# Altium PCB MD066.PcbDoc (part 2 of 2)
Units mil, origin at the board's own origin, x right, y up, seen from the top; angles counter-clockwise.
Board outline 4255 x 2850 mil, 4 copper layers (Top Layer, Ground, Power, Bottom Layer), stack 61.6 mil thick; 158 components, 78 nets, 405 pads, 639 vias.
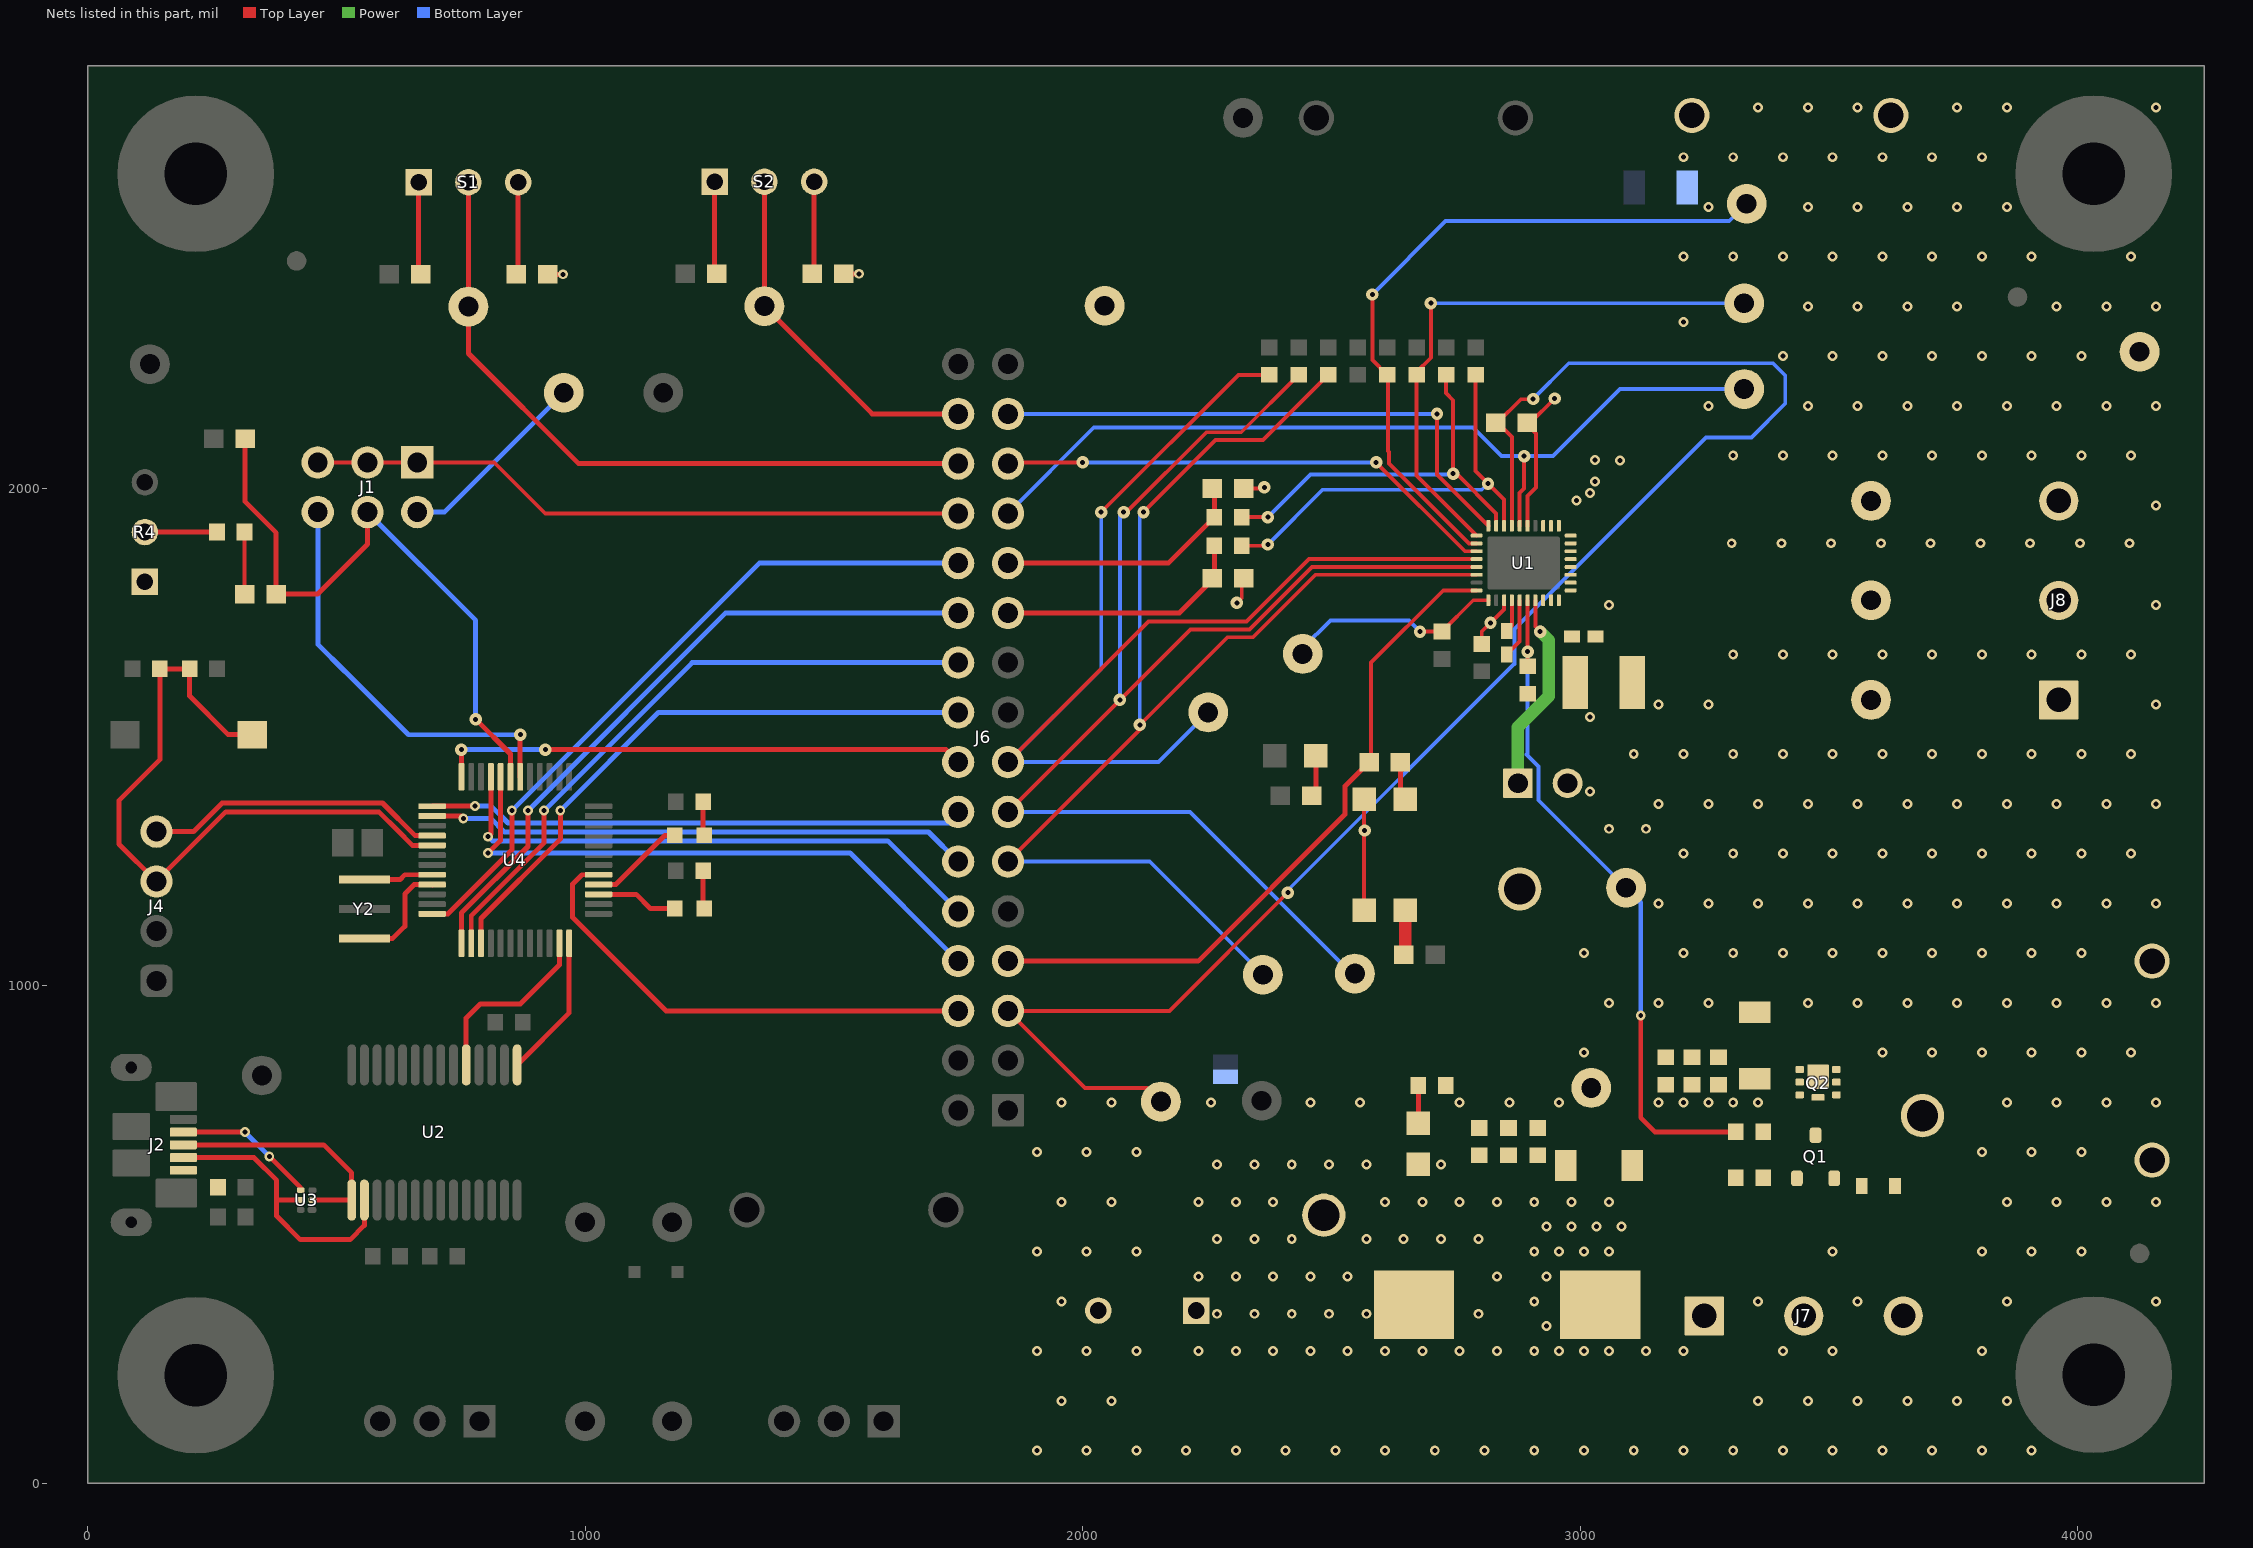
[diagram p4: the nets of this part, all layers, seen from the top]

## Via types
v1: diameter 20, hole 10, Top Layer to Bottom Layer, tented both sides, 600 vias
v2: diameter 25, hole 10, Top Layer to Bottom Layer, tented both sides, 30 vias
v3: diameter 19.68, hole 7.87, Top Layer to Bottom Layer, tented both sides, 8 vias
v4: diameter 25, hole 10, Top Layer to Bottom Layer, 1 vias

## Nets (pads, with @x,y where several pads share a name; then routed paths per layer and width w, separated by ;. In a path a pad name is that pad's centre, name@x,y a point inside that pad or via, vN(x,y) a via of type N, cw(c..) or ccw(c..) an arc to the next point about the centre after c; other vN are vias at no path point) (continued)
AVDD: C5.2 D1.1 D2.1 R1.2 R2.2 R4.1 R10.2 R13.2 R14.2 TP11.1 U1.3 U1.23 | length 803.3
  Top Layer w7.87: v2(2310,1770) 2320.06,1780.06 R14.2@2320.06,1820 ; R13.2@2320.06,2000 2362.84,2000 v2(2365.34,2002.5) ; D1.1@2566.16,1152.5 D2.1@2566.16,1375 ; C5.2@2802.5,1687.56 2802.5,1712.3 v2(2820,1729.8) 2847.26,1757.07 U1.3@2847.26,1775.39 ; U1.23@2894.51,1925 2894.51,1984.74 2911.81,2002.04 2911.81,2110.28 2889.59,2132.5 2900.67,2132.5 v2(2949.16,2180.99)
  Top Layer w10: R1.2@920.5,2430.7 v1(955.44,2430.7) ; R2.2@1515.5,2431.7 v1(1550.44,2431.7)
  Power w7.87: v2(2567.02,1312.5) v2@2567.02,1313
BRAKE: J6.27 U1.31 | length 1017.2
  Top Layer w7.87: J6.27@1850,2050 1852.5,2052.5 v4(2000,2052.5) ; v2(2590,2052.5) 2768.68,1873.82 U1.31@2792.15,1873.82
  Bottom Layer w7.87: v4(2000,2052.5) v2(2590,2052.5)
BRAKE_SW: J6.28 S1.2 TP2.1 | length 1420.5
  Top Layer w10: S1.2@765.44,2615.7 TP2.1@765.44,2365.7 765.44,2271.54 986.97,2050 J6.28@1750,2050
CPH: C7.1 U1.5 | length 119.9
  Top Layer w7.87: C7.1@2852.5,1666.38 2878.76,1692.64 U1.5@2878.76,1775.39
CPL: C7.2 U1.4 | length 88.2
  Top Layer w7.87: C7.2@2852.5,1713.62 2863.01,1724.13 U1.4@2863.01,1775.39 2863.01,1753.32
DACOUT1: J6.11 R28.1 TP15.1 U1.34 | length 2736.6
  Top Layer w7.87: J6.11@1850,1250 2117.5,1517.5 2115,1520 v2(2115,1525) 2291,1701 2342.48,1701 2468.05,1826.57 U1.34@2792.15,1826.57 ; v2(2122.5,1952.5) 2267.34,2097.34 2362.5,2097.34 R28.1@2493.6,2228.44
  Top Layer w10: J6.11@1850,1250 J6.11@1875,1250
  Bottom Layer w7.87: J6.11@1850,1250 2135,1250 TP15.1@2362.5,1022.5 ; v2(2115,1525) 2115,1945 v2(2122.5,1952.5)
DACOUT2: J6.13 R29.1 TP16.1 U1.33 | length 2824.9
  Top Layer w7.87: J6.13@1850,1350 v2(2075,1575) 2216.75,1716.75 2335.95,1716.75 2461.52,1842.32 U1.33@2792.15,1842.32 ; v2(2082.5,1952.5) 2088.12,1952.5 2248.71,2113.09 2318.95,2113.09 R29.1@2434.3,2228.44
  Bottom Layer w7.87: J6.13@1850,1350 2215.62,1350 2540.62,1025 TP16.1@2547.5,1025 ; v2(2075,1575) 2075,1945 v2(2082.5,1952.5)
DACOUT2/SOX: J6.15 R27.1 TP17.1 U1.32 | length 2587.1
  Top Layer w7.87: J6.15@1850,1450 2132.5,1732.5 2329.43,1732.5 2455,1858.07 U1.32@2792.15,1858.07 ; v2(2037.5,1952.5) 2313.44,2228.44 R27.1@2375,2228.44
  Bottom Layer w7.87: v2(2037.5,1952.5) 2037.5,1637.5 J6.15@1850,1450 2152.5,1450 TP17.1@2252.5,1550
DIR: J6.29 U1.28 | length 1130.4
  Top Layer w7.87: v2(2712.5,2150) 2712.5,2028.12 2815.62,1925 U1.28@2815.77,1925
  Bottom Layer w7.87: J6.29@1850,2150 v2(2712.5,2150)
DIR_SW: J6.30 S2.2 TP3.1 | length 729.3
  Top Layer w10: S2.2@1360.44,2616.7 TP3.1@1360.44,2366.7 1577.14,2150 J6.30@1750,2150
DM: J2.2 U2.16 U3.5 | length 585.4
  Top Layer w10: J2.2@192.22,655 334.14,655 380,609.14 380,570 ; U3.5@428.19,569.59 380.41,569.59 380,570 ; U2.16@556.23,569.59 556.23,518.73 527.5,490 427.5,490 380,537.5 380,570
DP: J2.3 U2.15 U3.2 | length 495.3
  Top Layer w10: J2.3@192.22,680.59 474.41,680.59 530.64,624.36 U2.15@530.64,569.59 U3.2@451.81,569.59
DVDD: C3.2 TP12.1 U1.1 | length 443.3
  Top Layer w7.87: v2(2678.37,1712.5) 2722.44,1712.5 C3.2@2722.5,1712.56 2785.33,1775.39 U1.1@2815.77,1775.39
  Bottom Layer w7.87: TP12.1@2442.5,1667.5 2442.5,1679 2498.5,1735 2655.87,1735 v2(2678.37,1712.5)
EXT_CLK: R24.1 TP8.1 U1.30 | length 1424.5
  Top Layer w7.87: v2(2582.5,2390) 2582.5,2258.14 R24.1@2612.2,2228.44 2614.31,2226.33 2614.31,2075 2615.71,2073.6 2615.71,2050.45 2776.6,1889.57 U1.30@2792.15,1889.57
  Bottom Layer w7.87: v2(2582.5,2390) 2730,2537.5 3300,2537.5 TP8.1@3335,2572.5
EXT_SPEED: J1.2 TP1.1 | length 409.1
  Top Layer w10: J1.2@662.5,1937.27 J1.2@662.5,1952.5
  Bottom Layer w10: J1.2@662.5,1952.5 716.95,1952.5 TP1.1@956.95,2192.5
EXT_WD: R23.1 TP7.1 U1.29 | length 1159
  Top Layer w7.87: v2(2700,2372.5) v2(2700,2372.5) 2700.04,2262.92 2671.5,2234.38 R23.1@2671.5,2228.44 2671.5,2025.96 U1.29@2792.15,1905.32
  Bottom Layer w7.87: v2(2700,2372.5) TP7.1@3330,2372.5
FG: J6.5 R10.1 TP35.1 U1.25 | length 3408.8
  Top Layer w7.87: TP35.1@2157.5,767.5 2130,795 2005,795 J6.5@1850,950 2175,950 v2(2412.5,1187.5) ; U1.25@2863.01,1925 2863.01,2103.96 2834.47,2132.5 2881.37,2179.41 2905,2179.41 v2(2905.59,2180)
  Bottom Layer w7.87: v2(2412.5,1187.5) 2412.5,1192.36 2867.64,1647.5 2868.19,1647.5 2868.19,1717.5 3253.19,2102.5 3344.38,2102.5 3412.5,2170.62 3412.5,2227.5 3388.19,2251.81 2977.41,2251.81 v2(2905.59,2180)
ID: J2.4 U3.4 | length 287.3
  Top Layer w10: J2.4@192.22,706.18 v1(316.27,706.18) ; v1(365,657.5) 428.19,594.31 U3.4@428.19,589.28
  Bottom Layer w10: v1(316.27,706.18) 364.95,657.5 v1(365,657.5)
MCX_SCL: J6.23 R13.1 R15.1 | length 510.8
  Top Layer w10: J6.23@1850,1850 2172.44,1850 R15.1@2264.94,1942.5 R13.1@2264.94,2000
MCX_SDA: J6.21 R14.1 R16.1 | length 508.9
  Top Layer w10: J6.21@1850,1750 2194.94,1750 2264.94,1820 R16.1@2264.94,1885
MSP_A1_P1.1: J6.12 U4.2 | length 1094.7
  Top Layer w10: U4.2@693.3,1341.67 750.24,1341.67 v1(755,1336.91)
  Bottom Layer w10: v1(755,1336.91) 810.31,1336.91 837.6,1309.63 1690.37,1309.63 J6.12@1750,1250
MSP_A2_P1.2: J6.14 U4.1 | length 1070.7
  Top Layer w10: U4.1@693.3,1361.36 v1(778.64,1361.36)
  Bottom Layer w10: v1(778.64,1361.36) 811.14,1361.36 845,1327.5 J6.14@1750,1327.5
MSP_A3_P1.3: J6.16 U4.48 | length 1064.6
  Top Layer w10: U4.48@751.37,1419.43 U4.48@751.37,1420.41 v2(751.37,1475) ; v2(920,1475) 1725,1475 J6.16@1750,1450
  Bottom Layer w10: v2(751.37,1475) v2(920,1475)
MSP_ALARM_P3.2: J6.10 U4.45 | length 1130.1
  Top Layer w10: v1(805,1300) 810.43,1305.43 810.43,1419.43 U4.45@811.33,1420.33
  Bottom Layer w10: v1(805,1300) 813.25,1291.75 1608.25,1291.75 J6.10@1750,1150
MSP_CLK_P4.5: J6.20 U4.14 | length 1282.1
  Top Layer w10: U4.14@771.06,1086.75 771.06,1141.3 917.5,1287.74 v1(917.5,1352.5)
  Bottom Layer w10: v1(917.5,1352.5) 1215,1650 J6.20@1750,1650
MSP_FGOUT_P2.1: J6.6 U4.29 | length 978.8
  Top Layer w10: U4.29@1025.98,1223.56 993.56,1223.56 975,1205 975,1137.5 1162.5,950 J6.6@1750,950
MSP_LED0_P2.2: D6.2 U4.28 | length 195.1
  Top Layer w10: U4.28@1025.98,1203.88 1061.68,1203.88 1160.49,1302.7 D6.2@1180.11,1302.7
MSP_LED1_P2.2: D7.2 U4.27 | length 166
  Top Layer w10: U4.27@1025.98,1184.19 1102.5,1184.19 1131.1,1155.59 D7.2@1180.11,1155.59
MSP_nFAULT_P3.3: J6.8 U4.44 | length 1197.4
  Top Layer w10: v1(805,1267.5) 829.63,1292.13 829.63,1418.94 U4.44@830.11,1419.43
  Bottom Layer w10: v1(805,1267.5) 1532.5,1267.5 J6.8@1750,1050
MSP_RX_P4.3: U2.5 U4.23 | length 370.2
  Top Layer w10: U2.5@760.96,841.24 760.96,935.49 789.25,963.78 869.75,963.78 948.22,1042.25 U4.23@948.22,1086.75
MSP_SBWTCK: J4.4 U4.4 | length 617.6
  Top Layer w10: J4.4@145.74,1302.3 137.86,1310.18 212.58,1310.18 270.27,1367.87 592.8,1367.87 658.37,1302.3 U4.4@693.3,1302.3
MSP_SBWTDIO/nRST: C14.1 J4.3 R31.1 S4.1 U4.5 | length 1406.7
  Top Layer w10: S4.1@330.96,1505.27 282.5,1505.27 204.94,1582.83 R31.1@204.94,1637.5 C14.1@145.06,1637.5 145.06,1455 62.5,1372.44 62.5,1285.54 137.86,1210.18 277.68,1350 585.35,1350 624.97,1310.37 ; 625.02,1310.37 650.41,1284.98 ; 650.41,1284.94 652.73,1282.62 U4.5@693.3,1282.62
MSP_SIMO/SDA_P4.6: J6.22 U4.13 | length 1350.7
  Top Layer w10: U4.13@751.37,1086.75 751.37,1146.89 885,1280.52 v1(885,1352.5)
  Bottom Layer w10: v1(885,1352.5) 1282.5,1750 J6.22@1750,1750
MSP_SOMI/SCL_P4.7: J6.24 U4.12 | length 1396.5
  Top Layer w10: U4.12@694.21,1145.73 693.3,1144.82 724.03,1144.82 852.5,1273.3 v1(852.5,1352.5)
  Bottom Layer w10: v1(852.5,1352.5) 1350,1850 J6.24@1750,1850
MSP_STE_P4.4: J6.18 U4.15 | length 1213.5
  Top Layer w10: U4.15@790.74,1086.75 790.74,1135.71 950,1294.96 v1(950,1352.5)
  Bottom Layer w10: v1(950,1352.5) 1147.5,1550 J6.18@1750,1550
MSP_TB0.1: J1.6 U4.42 | length 833.3
  Top Layer w10: U4.42@869.48,1420.41 869.48,1505 v2(869.75,1505.27)
  Bottom Layer w10: J1.6@462.5,1952.5 462.5,1686.83 517.19,1632.15 517.73,1632.15 644.88,1505 869.48,1505 v2(869.75,1505.27)
MSP_TX_P4.2: U2.1 U4.24 | length 288.8
  Top Layer w10: U2.1@863.32,841.24 967.91,945.83 U4.24@967.91,1086.75
MSP_XIN_P2.7: U4.8 Y2.1 | length 141.2
  Top Layer w10: Y2.1@556.22,1213.72 627.85,1213.72 637.69,1223.56 U4.8@693.3,1223.56
MSP_XOUT_P2.6: U4.9 Y2.3 | length 221.8
  Top Layer w10: Y2.3@556.83,1095 Y2.3@556.22,1095.61 613.11,1095.61 637.5,1120 637.5,1185 656.38,1203.88 693.3,1203.88 U4.9@693.3,1202.97
NetC17_1: C17.1 C18.1 C19.1 C20.1 L4.1 Q2.1 Q2.2 Q2.5 Q2.6 Q2.7
  other v1: 2908,266 2958,266 3008,266 3058,266 2933,316 2908,366 2933,416 2908,466 2958,466 3008,466 3058,466 2933,516 2983,516 3033,516 3083,516 3158,766 3208,766 3258,766 3308,766 3358,766
NetD1_2: D1.2 R17.2 | length 90.5
  Top Layer w25: D1.2@2648.84,1152.5 2648.84,1063.6 R17.2@2649.94,1062.5
NetD2_2: D2.2 R18.2 | length 79.1
  Top Layer w10: R18.2@2639,1450 2639,1384.84 D2.2@2648.84,1375
NetD3_2: D3.2 R19.2 | length 83.5
  Top Layer w10: R19.2@2460.48,1382.5 2468.84,1390.86 D3.2@2468.84,1462.5
NetD4_2: D4.2 R20.2 | length 76.2
  Top Layer w10: D4.2@2675,723.84 R20.2@2675,800
NetD6_1: D6.1 R32.1 | length 68.3
  Top Layer w10: R32.1@1237.2,1370.2 1237.2,1304.67 D6.1@1239.17,1302.7
NetD7_1: D7.1 R33.1 | length 76.7
  Top Layer w10: R33.1@1237.2,1231.43 1237.2,1157.56 D7.1@1239.17,1155.59
NetD8_2: D8.2 Q1.2
NetJ2_1: J2.1 L3.2
NetQ1_1: Q1.1 R35.1
NetQ1_3: Q1.3 Q2.3 R34.2
NetR1_1: R1.1 S1.3 | length 185
  Top Layer w10: R1.1@865.44,2430.7 S1.3@865.44,2615.7
NetR2_1: R2.1 S2.3 | length 185
  Top Layer w10: R2.1@1460.44,2431.7 S2.3@1460.44,2616.7
NetR4_2: R4.2 R5.2 | length 144.9
  Top Layer w10: R4.2@115,1912.5 R5.2@259.94,1912.5
NetR5_1: R5.1 R9.2 | length 125.4
  Top Layer w7.87: R5.1@315.06,1912.5 315.06,1788.44 R9.2@316,1787.5
NetR6_2: R6.2 S1.1 | length 185
  Top Layer w10: S1.1@665.44,2615.7 665.44,2430.76 R6.2@665.5,2430.7
NetR7_2: R7.2 S2.1 | length 185
  Top Layer w10: R7.2@1260.44,2431.7 S2.1@1260.44,2616.7
nFAULT: J6.7 R18.1 U1.36 | length 1401.2
  Top Layer w7.87: R18.1@2579.94,1450 2579.94,1650.02 2725,1795.08 U1.36@2792.15,1795.08
  Top Layer w10: J6.7@1850,1050 2232.5,1050 2527.5,1345 2527.5,1401.79 2575.71,1450 R18.1@2579.94,1450
OUTA: J8.1 TP5.1 U1.11 U1.12
OUTB: J8.2 TP6.1 U1.14 U1.15
OUTC: J8.3 TP9.1 U1.17 U1.18
PGND: C4.2 C6.2 C16.2 C17.2 C18.2 C19.2 C20.2 C21.2 C22.2 C23.2 C24.2 J7.2 NT2.2 R20.1 R35.2 R36.2 TP25.1 TP28.1 TP28.2 TP29.1 TP29.2 TP34.1 U1.10 U1.13 U1.16 U1.19
  other v1: 1908,66 2008,66 2108,66 2208,66 2308,66 2408,66 2508,66 2608,66 2708,66 2808,66 2908,66 3008,66 3108,66 3208,66 3308,66 3408,66 3508,66 3608,66 3708,66 3808,66 3908,66 1958,166 2058,166 3358,166 3458,166 3558,166 3658,166 3758,166 3858,166 1908,266 2008,266 2108,266 3408,266 3508,266 3808,266 1958,366 3358,366 3558,366 3858,366 4158,366 1908,466 2008,466 2108,466 3508,466 3808,466 3908,466 4008,466 1958,566 2058,566 3058,566 3858,566 3958,566 4058,566 4158,566 1908,666 2008,666 2108,666 3808,666 3908,666 4008,666 1958,766 2058,766 2258,766 2458,766 2558,766 2758,766 2858,766 2958,766 3858,766 3958,766 4058,766 4158,766 3008,866 3608,866 3708,866 3808,866 3908,866 4008,866 4108,866 3058,966 3158,966 3258,966 3458,966 3558,966 3658,966 3758,966 3858,966 3958,966 4058,966 4158,966 3008,1066 3208,1066 3308,1066 3408,1066 3508,1066 3608,1066 3708,1066 3808,1066 3908,1066 4008,1066 3158,1166 3258,1166 3358,1166 3458,1166 3558,1166 3658,1166 3758,1166 3858,1166 3958,1166 4058,1166 4158,1166 3208,1266 3308,1266 3408,1266 3508,1266 3608,1266 3708,1266 3808,1266 3908,1266 4008,1266 4108,1266 3158,1366 3258,1366 3358,1366 3458,1366 3558,1366 3658,1366 3758,1366 3858,1366 3958,1366 4058,1366 4158,1366 3108,1466 3208,1466 3308,1466 3408,1466 3508,1466 3608,1466 3708,1466 3808,1466 3908,1466 4008,1466 4108,1466 3158,1566 3258,1566 4158,1566 3308,1666 3408,1666 3508,1666 3608,1666 3708,1666 3808,1666 3908,1666 4008,1666 4108,1666 3058,1766 4158,1766 3305,1890 3405,1890 3505,1890 3605,1890 3705,1890 3805,1890 3905,1890 4005,1890 4105,1890 4158,1966 3308,2066 3408,2066 3508,2066 3608,2066 3708,2066 3808,2066 3908,2066 4008,2066 4108,2066 3258,2166 3458,2166 3558,2166 3658,2166 3758,2166 3858,2166 3958,2166 4058,2166 4158,2166 3408,2266 3508,2266 3608,2266 3708,2266 3808,2266 3908,2266 4008,2266 3208,2335 3458,2366 3558,2366 3658,2366 3758,2366 3958,2366 4058,2366 4158,2366 3208,2466 3308,2466 3408,2466 3508,2466 3608,2466 3708,2466 3808,2466 3908,2466 4108,2466 3258,2566 3458,2566 3558,2566 3658,2566 3758,2566 3858,2566 3208,2666 3308,2666 3408,2666 3508,2666 3608,2666 3708,2666 3808,2666 3358,2766 3458,2766 3558,2766 3758,2766 3858,2766 4158,2766
POT: C2.1 J1.4 R9.1 U4.43 | length 1279
  Top Layer w10: C2.1@316.5,2100 316.5,1973.5 379,1911 R9.1@379,1787.5 461.85,1787.5 562.5,1888.15 J1.4@562.5,1952.5 ; v2(780,1536.14) 849.8,1466.34 U4.43@849.8,1420.41
  Bottom Layer w10: J1.4@562.5,1952.5 780,1735 v2(780,1536.14)
SCL: R15.2 R22.1 U1.27 | length 817
  Top Layer w7.87: R15.2@2320.06,1942.5 v2(2372.5,1942.5) ; R22.1@2730.8,2228.44 2730.8,2191.7 2745,2177.5 v2(2745,2030) 2751.52,2030 2831.52,1950 U1.27@2831.52,1925
  Bottom Layer w7.87: v2@2379.38,1942.5 v2(2372.5,1942.5) 2458.19,2028.19 2743.19,2028.19 v2(2745,2030)
SDA: R16.2 R21.1 U1.26 | length 873.8
  Top Layer w7.87: R16.2@2320.06,1885 2370,1885 v2(2372.5,1887.5) ; R21.1@2790.1,2228.44 2790.1,2034.9 v2(2815,2010) 2847.26,1977.74 U1.26@2847.26,1925
  Bottom Layer w7.87: v2(2372.5,1887.5) 2482.5,1997.5 2802.5,1997.5 v2(2815,2010)
SPEED/WAKE: J6.25 TP14.1 U1.24 | length 1774.8
  Top Layer w7.87: U1.24@2878.76,1925 2878.76,1991.26 2887.5,2000 v2(2887.5,2065)
  Bottom Layer w7.87: J6.25@1850,1950 2022.5,2122.5 2785,2122.5 2842.5,2065 v2(2887.5,2065) 2945.62,2065 3080.62,2200 TP14.1@3330,2200
SPEED_IN: J1.1 J1.3 J1.5 J6.26 | length 1338.2
  Top Layer w7.87: J1.5@462.5,2052.5 J1.3@562.5,2052.5 J1.1@662.5,2052.5 817.27,2052.5 919.77,1950 J6.26@1750,1950 J6.26@1744.19,1944.19
VBAT: D8.1 J7.3 Q2.4 Q2.8 TP23.1
VCP: C1.1 R34.1 TP13.1 U1.6 | length 1379.6
  Top Layer w7.87: U1.6@2894.51,1775.39 v2(2894.51,1672.01) 2894.51,1642.99 C1.1@2894.94,1642.56 C1.1@2902.5,1650.12
  Top Layer w10: v1(3122.11,940.29) 3122.11,735.08 3150.55,706.64 R34.1@3313.4,706.64
  Bottom Layer w7.87: v2(2894.51,1672.01) 2894.51,1467.33 2892.5,1465.32 2916.73,1441.09 2916.73,1373.27 TP13.1@3092.5,1197.5
  Bottom Layer w10: TP13.1@3092.5,1197.5 3122.11,1167.89 v1(3122.11,940.29)
VIN_AVDD: JP1.1 TP10.1 U1.7 | length 405.1
  Top Layer w7.87: U1.7@2910.26,1775.39 2910.26,1722.24 v2(2920,1712.5)
  Power w25: JP1.1@2875,1407.5 2875,1520.22 2937.5,1582.72 2937.5,1695 v2(2920,1712.5)
VM: C1.2 C4.1 C6.1 C16.1 C21.1 C22.1 C23.1 C24.1 D4.1 J7.1 JP1.2 L4.2 TP24.1 U1.8 U1.9 U1.20 U1.21
  other v1: 2233,266 2308,266 2383,266 2458,266 2533,266 2608,266 2683,266 2758,266 2833,266 3133,266 3208,266 2270.5,341 2345.5,341 2420.5,341 2495.5,341 2570.5,341 2795.5,341 2233,416 2308,416 2383,416 2458,416 2533,416 2833,416 2270.5,491 2345.5,491 2420.5,491 2570.5,491 2645.5,491 2720.5,491 2795.5,491 2233,566 2308,566 2383,566 2608,566 2683,566 2758,566 2833,566 2908,566 2983,566 2270.5,641 2345.5,641 2420.5,641 2495.5,641 2570.5,641 2720.5,641 3058,1316 3133,1316 3020.5,1391 3020.5,1541 2992.5,1976.3 3020.5,1991 3030,2014.18 3030,2057.11 3080.75,2056.61
pads on no net: FID1.1 FID2.1 FID3.1 H1.1 H2.1 H3.1 H4.1 H5.0 H6.0 H7.0 H8.0 J6.3 J6.4 J6.17 J6.19 J6.31 J6.32 LBL1.0 SH-J1.0 SH-J2.0 SH-J3.0 SH-J4.0 SH-J5.0 SH-J6.0 SH-J7.0 SH-J8.0 SH-J9.0 SH-J10.0 SH-J11.0 SH-J12.0 SH-J13.0 SH-J14.0 SH-J15.0 SH-J16.0 SH-J17.0 SH-J18.0 SH-J19.0 SH-J21.0 U2.2 U2.3 U2.6 U2.8 U2.9 U2.10 U2.11 U2.12 U2.13 U2.14 U2.19 U2.22 U2.23 U2.24 U2.27 U2.28 U3.1 U4.3 U4.10 U4.11 U4.16 U4.17 U4.18 U4.19 U4.20 U4.21 U4.22 U4.25 U4.26 U4.30 U4.31 U4.32 U4.33 U4.34 U4.35 U4.36 U4.37 U4.38 U4.39 U4.40 U4.41 U4.46 U4.47
copper on no net: | length 8.8
  Bottom Layer w10: 1521.27,2365.7 1527.5,2359.47

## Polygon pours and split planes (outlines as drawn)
AGND on Top Layer "TOP_LAYER_AGND_P380" (solid, pour order 380): 2953.48,2850 2955.98,2847.5 3162.5,2847.5 3162.5,2072.5 3162.16,2072.16 3128.99,2072.16 3002.5,1945.67 2953.48,1945.67 2953.48,832.5 1800,832.5 1800,0 0,0 0,2850
PGND on Top Layer "TOP_LAYER_PGND_P381" (solid, pour order 381): 3167.91,2850 3167.91,2070.26 3164.4,2066.75 3131.23,2066.75 3004.74,1940.26 2953.48,1940.26 2953.48,832.5 1800,832.5 1800,0 4255,0 4255,2850
VM on Top Layer "TOP_LAYER_VM_P373" (solid, remove dead copper, pour order 373): 2936.88,1617.5 2930.44,1611.06 2870.33,1611.06 2870.33,1542.17 2936.88,1475 2936.88,1255 3145.53,1255 3145.53,1331.97 3062.5,1415 3062.5,1675 3054.68,1682.82 3007.5,1682.82 3007.5,1722.18 2972.03,1757.66 2949.63,1757.66 2949.63,1783.88 2946,1787.5 2919.55,1787.5 2919.55,1767.48 2919.03,1766.96 2937.15,1748.84 2937.56,1675.68 2936.88,1675
VM on Top Layer "TOP_LAYER_VM_P379" (solid, pour order 379): 2946,1938.19 2953.48,1945.67 3003.17,1945.67 3120.47,2062.97 3120.47,2074.06 3012.5,2074.06 3012.5,2024.73 2922.5,1934.73 2922.5,1910.13 2946,1910.13
VIN_AVDD on Top Layer "TOP_LAYER_VIN_AVDD_P372" (solid, remove dead copper, pour order 372): 2687.5,1325 2842.5,1480 2842.5,1559.49 2932.5,1559.49 2932.5,1144.82 2687.5,1144.82
OUTA on Top Layer "TOP_LAYER_OUTA_P378" (solid, remove dead copper, pour order 378): 3120.47,1814.53 3295,1640 4110,1640 4119.98,1630.02 4119.98,1515 3351.52,1515 3076.82,1789.69 2968.24,1789.69 2967.5,1790.44 2968.87,1791.81 2968.87,1814.53
OUTB on Top Layer "TOP_LAYER_OUTB_P377" (solid, remove dead copper, pour order 377): 3065,1862.5 4118.02,1857.5 4118.15,1716.1 3274.42,1716.1 3151.95,1838.58 2969.42,1838.58 2968.74,1862.5
OUTC on Top Layer "TOP_LAYER_OUTC_P376" (solid, remove dead copper, pour order 376): 3032.5,1885 3066.65,1919.15 4112.5,1919.15 4112.5,2032.5 3132.5,2032.5 3011.12,1911.12 2967.5,1911.12 2967.5,1885
5VCC on Top Layer "TOP_LAYER_5VCC_P375" (solid, remove dead copper, pour order 375): 707.79,434.34 603.09,434.34 603.09,481.84 707.79,481.84
VBAT on Top Layer "TOP_LAYER_VBAT_P374" (solid, remove dead copper, pour order 374): 3749.99,249.14 3603.46,249.14 3603.46,639.95 3459.35,639.94 3459.34,843.72 3749.99,843.72
NetC17_1 on Top Layer "TOP_LAYER_NETC17_1_P370" (solid, remove dead copper, pour order 370): 3107.8,535.39 2852.5,535.39 2852.5,253.93 3107.8,253.93
VM on Top Layer "TOP_LAYER_VM_P371" (solid, remove dead copper, pour order 371): 3015.96,679.14 2150,679.14 2150,164.14 2888.46,164.14 3308.46,164.14 3308.46,289.14 3308.46,376.64 3198.46,376.64 3198.46,289.14 3015.96,289.14
NetD8_2 on Top Layer "TOP_LAYER_NETD8_2_P369" (solid, remove dead copper, pour order 369): 3595.96,641.64 3487.66,641.64 3485.96,639.94 3485.96,556.64 3595.96,556.64
NetQ1_3 on Top Layer "TOP_LAYER_NETQ1_3_P368" (solid, remove dead copper, pour order 368): 3491.05,639.95 3334.15,639.95 3334.15,728.37 3337.42,731.64 3427.95,731.64 3427.95,792.97 3455.52,792.97 3455.52,733.23 3453.93,731.64 3491.05,731.64
NetC17_1 on Top Layer "TOP_LAYER_NETC17_1_P367" (solid, remove dead copper, pour order 367): 3528.88,791.21 3424.06,791.21 3424.06,735.79 3424.89,734.96 3424.89,724.14 3133.88,724.14 3133.46,723.73 3133.46,819.14 3303.21,819.14 3303.46,819.39 3303.46,854.14 3528.88,854.14
NetQ1_1 on Top Layer "TOP_LAYER_NETQ1_1_P366" (solid, remove dead copper, pour order 366): 3485.96,556.64 3340.96,556.64 3340.96,639.94 3485.96,639.94
NetJ2_1 on Top Layer "TOP_LAYER_NETJ2_1_P365" (solid, remove dead copper, pour order 365): 327.14,563.32 176.94,563.32 177.14,645.59 327.14,645.59
5V_USB on Top Layer "TOP_LAYER_5V_USB_P364" (solid, remove dead copper, pour order 364): 374.78,613.98 299.11,613.98 299.11,508.2 374.78,508.2
AGND on Power "POWER_AGND_P388" (solid, remove dead copper, pour order 388): 0,2850 4255,2850 4255,0 0,0
AVDD on Power "POWER_AVDD_P387" (solid, remove dead copper, pour order 387): 2275,1800 2275,1286.52 2697.5,1286.52 2697.5,1431.02 2696.02,1432.5 2342.5,1432.41 2342.5,1690 2365,1712.5 2970,1712.5 2970,1785 2350,1785 2335,1800 2335,1942.62 2464.88,2072.5 3075,2072.5 3075,2200 2200,2200 2125,2275 2125,2397.5 2052.5,2470 1930,2470 874.7,2470 825,2420.3 825,2050 625,1850 75,1850 75,1775 675,1775 900,2000 900,2295 1000,2395 1880,2395 2275,2000
3V3_MCU on Power "POWER_3V3_MCU_P386" (solid, remove dead copper, pour order 386): 1225,1182.5 1225,537.5 1550,212.5 1550,52.5 1450,52.5 1450,162.5 1125.19,487.31 1125,1125 1075,1175 1057.5,1192.5 372.5,1192.5 235,1055 52.5,1055 52.5,1162.5 200,1162.5 257.5,1220 257.5,1657.5 337.5,1657.5 337.5,1340 1075,1340 1075,1400 1200,1400 1200,1207.5
VM on Power "POWER_VM_P385" (solid, pour order 385): 2981.17,1475 2936.88,1475 2936.88,1013.12 2937.5,1012.5 2605.41,680.41 2155.41,680.41 2150,675 2150,200 3300,200 3300,1475 3300,2074.06 3012.5,2074.06 3012.5,2024.73 2922.5,1934.73 2922.5,1910.13 2946,1910.13 2948.37,1912.5 3000,1912.5 3000,1493.83
5V_USB on Power "POWER_5V_USB_P383" (solid, remove dead copper, pour order 383): 437.5,622.5 302.5,622.5 302.5,492.5 437.5,492.5
AGND on Bottom Layer "BOTTOM_LAYER_AGND_P393" (solid, pour order 393): 2953.48,2850 2955.98,2847.5 3162.5,2847.5 3162.5,2072.5 3162.16,2072.16 3128.99,2072.16 3002.5,1945.67 2953.48,1945.67 2953.48,832.5 1800,832.5 1800,0 0,0 0,2850
5V_USB on Bottom Layer "BOTTOM_LAYER_5V_USB_P389" (solid, remove dead copper, pour order 389): 290,490 440,490 440,875 290,875
PGND on Bottom Layer "BOTTOM_LAYER_PGND_P394" (solid, pour order 394): 3167.91,2850 3167.91,2070.26 3164.4,2066.75 3131.23,2066.75 3004.74,1940.26 2953.48,1940.26 2953.48,832.5 1800,832.5 1800,0 4255,0 4255,2850
no net on Bottom Layer "BOTTOM_LAYER_NONET_P391" (solid, remove dead copper, pour order 391): 3100.58,1412.5 3175,1338.08 3175,1100 2960,1100 2960,1412.5
no net on Bottom Layer "BOTTOM_LAYER_NONET_P390" (solid, remove dead copper, pour order 390): 2871.92,1412.5 2750,1290.58 2750,1100 2960,1100 2960,1412.5
NetC17_1 on Bottom Layer "BOTTOM_LAYER_NETC17_1_P392" (solid, pour order 392): 3133.72,819.39 3133.46,536.64 2852.13,536.64 2852.13,253.69 3170.74,253.69 3170.74,392.5 3425.96,392.5 3425.96,819.39
AGND on Ground "GROUND_AGND_P382" (solid, remove dead copper, pour order 382): 0,2850 4255,2850 4255,0 0,0 0,1695

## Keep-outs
Keep-Out Layer:
  text ".Layer_Name" at 577,-858.49 h60

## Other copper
Top Layer:
  text ".Layer_Name" at 577,-858.49 h60
Bottom Layer:
  text ".Layer_Name" at 577,-858.49 h60

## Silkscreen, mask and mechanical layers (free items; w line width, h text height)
Top Overlay:
  rectangle: 3912.61,1226.56 4069.36,1287.5
  lines w8: 412.5,2102.5 412.5,2327.5 711.18,2327.5 ; 712.5,2102.5 712.5,2326.18 ; 1800,0 1800,2850 ; 1822.5,2682.5 2195,2682.5 ; 1824.32,2625.19 2195,2624.94 ; 1882.5,2565.38 1882.5,2747.5 ; 1925,2705 1910,2717.5 ; 1925,2730 1910,2717.5 ; 1965,2717.5 1910,2717.5 ; 2027.5,2565 2027.5,2742.5 ; 2062.5,2717.5 2117.5,2717.5 ; 2102.5,2705 2117.5,2717.5 ; 2102.5,2730 2117.5,2717.5 ; 2197.5,2747.5 1822.5,2747.5 1822.5,2565 2200,2565 2200,2747.5 ; 520,57.5 852.5,57.5 852.5,390 520,390 520,57.5 ; 1332.5,57.5 1332.5,390 1665,390 1665,57.5 1332.5,57.5
  lines w10: 711.18,2327.5 712.5,2326.18 ; 2325,2195 2325,2425 2835,2425 ; 2327.04,2195 2835,2195 2835,2424.5
  text "Switches" at 1855,2767.5 h30
  text "S" at 1842.5,2705 h30
  text "2" at 1842.5,2637.58 h30
  text "ABC" at 1897.5,2637.58 h30
  text "ACB" at 2050,2637.58 h30
  text "BRK" at 1897.5,2580 h30
  text "RUN" at 2050,2580 h30
  text "1" at 1847.5,2577.5 h30
  text "HW Variant" at 2878.11,2482.5 h30
  text "BRAKE" at 690.82,2467.5 h40
  text "DIR" at 1315,2462.5 h40
  text "SLEW" at 2377.5,2442.5 h30 r90
  text "CFG_2" at 2442.14,2442.5 h30 r90
  text "CFG_3" at 2506.79,2442.5 h30 r90
  text "ILIM" at 2571.43,2442.5 h30 r90
  text "LDANG" at 2636.07,2442.5 h30 r90
  text "CFG_1" at 2700.71,2442.5 h30 r90
  text "RMP_2" at 2765.36,2442.5 h30 r90
  text "RMP_1" at 2830,2442.5 h30 r90
  text "Resistors" at 2878.11,2440 h30
  text "NC" at 1620,2237.5 h30
  text "NC" at 1932.5,2235 h30
  text "DIR_SW" at 1502.5,2137.5 h30
  text "DIR" at 1932.5,2135 h30
  text "POT" at 572.32,2127.5 h30 r90
  text "EXT" at 677.5,2125 h30 r90
  text "INT_PWM" at 472.5,2122.5 h30 r90
  text "BRAKE_SW" at 1437.5,2037.5 h30
  text "BRAKE" at 1932.5,2035 h30
  text "POT" at 227.5,2032.5 h30
  text "C" at 3662.5,1955 h40
  text "C" at 4175,1955 h40
  text "SPEED_IN" at 1442.5,1935 h30
  text "SPEED/WAKE" at 1925,1935 h30
  text "MSP_SOMI/SCL" at 1322.5,1837.5 h30
  text "MCx_SCL" at 1932.5,1837.44 h30
  text "SPEED_SEL" at 410,1835 h40
  text "B" at 3662.5,1755 h40
  text "B" at 4175,1755 h40
  text "MSP_SIMO/SDA" at 1322.5,1737.5 h30
  text "MCx_SDA" at 1932.5,1737.69 h30
  text "MSP_CLK" at 1467.5,1637.5 h30
  text "NC" at 1932.5,1637.5 h30
  text "A" at 3662.5,1555 h40
  text "A" at 4175,1555 h40
  text "MSP_STE" at 1467.5,1537.5 h30
  text "NC" at 1932.5,1535 h30
  text "RST" at 390,1527.5 h30
  text "MSP_A3" at 1497.5,1437.5 h30
  text "DACOUT2/SOX" at 1932.5,1435 h30
  text "MSP_A2" at 1497.5,1337.5 h30
  text "DACOUT2" at 1932.5,1335 h30
  text "MCx8317AEVM" at 3501.02,1315 h50
  text "SBWTCK" at 225,1296.06 h30
  text "MSP_A1" at 1507.5,1237.5 h30
  text "DACOUT1" at 1932.5,1235 h30
  text "'.PRJ_Number''.PCB_Rev'-" at 3501.69,1232.5 h50
  text "SBWTDIO" at 225,1197.5 h30
  text "MSP_ALARM" at 1407.5,1137.5 h30
  text "ALARM" at 1932.5,1135 h30
  text "3.3V" at 225,1095 h30
  text "MSP_nFAULT" at 1377.5,1037.5 h30
  text "nFAULT" at 1932.5,1035 h30
  text "GND" at 225,997.5 h30
  text "MSP_FGOUT" at 1407.5,937.5 h30
  text "FGOUT" at 1932.5,935 h30
  text "NC" at 1617.5,835 h30
  text "NC" at 1932.5,835 h30
  text "AGND" at 1557.5,737.5 h30
  text "AGND" at 1932.5,735 h30
  text "3V3COM" at 1015,600 h30 r90
  text "3V3_MCU" at 1187.5,600 h30 r90
  text "5V_USB" at 600,197.5 h30 r90
  text "5V_EXT" at 800,197.5 h30 r90
  text "5V_EXT" at 1012.5,197.5 h30 r90
  text "3V3EXT" at 1190,197.5 h30 r90
  text "3V3COM" at 1415,197.5 h30 r90
  text "3V3EXT" at 1615,197.5 h30 r90
  text "5V_SEL" at 497.5,110 h40 r90
  text "Connect to VM to bypass" at 2360,105 h35
  text "3V3_SEL" at 1722.5,97.5 h40 r90
  text "VM" at 3217.5,72.5 h40
  text "PGND" at 3370,72.5 h40
  text "VBAT" at 3580,72.5 h40
  text "reverse polarity protection" at 2240,55 h35
  text ".Layer_Name" at 577,-858.49 h30
Bottom Overlay:
  text "C" at 3690,1955 h40
  text "C" at 4075,1955 h40
  text "B" at 3690,1755 h40
  text "B" at 4075,1755 h40
  text "A" at 3690,1555 h40
  text "A" at 4075,1555 h40
  text "VM" at 3285,220 h40
  text "PGND" at 3517.5,220 h40
  text "VBAT" at 3722.5,220 h40
  text ".Layer_Name" at 577,-858.49 h60
Top Paste:
  text ".Layer_Name" at 577,-858.49 h60
Bottom Paste:
  text ".Layer_Name" at 577,-858.49 h60
Top Solder:
  text ".Layer_Name" at 577,-858.49 h60
  text ".Layer_Name" at 577,-858.49 h60
Bottom Solder:
  text ".Layer_Name" at 577,-858.49 h60
Drill Guide:
  text ".Layer_Name" at 577,-858.49 h60
M1 Board Outline:
  the board outline again, w10
  text ".Layer_Name" at 577,-858.49 h60
M2 Board Dimensions:
  rectangle: 0,-275 125,-150
  rectangle: 125,-400 500,-275
  lines w7: 0,-275 1000,-275 ; 125,-400 125,-150 ; 250,-400 250,-150 ; 500,-400 500,-150 ; 750,-400 750,-150 ; 0,-400 1000,-400 1000,-150 0,-150 0,-400
  text ".Layer_Name" at 577,-858.49 h60
M3 3D STEP Top:
  text ".Layer_Name" at 577,-858.49 h60
M4 3D STEP Bottom:
  text ".Layer_Name" at 577,-858.49 h60
M5 Assembly Top:
  lines w10: -292,-930.17 6308,-930.17 ; -292,-726.83 6310,-726.83 ; -292,-523.5 -292,-1133.5 3713,-1133.5 6310,-1133.5 6310,-523.5 -291.5,-523.5 -291.5,-1133.5 1284,-1133.5 ; 2173,-1133.5 2173,-523.5 ; 3440,-726.83 3440,-523.5 ; 4280,-726.83 4280,-523.5 ; 4902,-1140 4902,-937.17
  text "COMPONENTS MARKED 'DNP' SHOULD NOT BE POPULATED." at 1153.5,-318.5 h60
  text "ASSEMBLY VARIANT:" at 1153,-434 h60
  text ".VariantName" at 2189,-434 h60
  text "PCB VIEWED FROM TOP SIDE" at -228.5,-655.67 h60
  text "BOARD #:" at 2248,-655.67 h60
  text ".PRJ_Number" at 2793.5,-655.67 h60
  text "REV:" at 3638,-655.67 h60
  text ".PCB_Rev" at 3929.5,-655.67 h60
  text "SVN REV:" at 4476,-655.67 h60
  text ".VersionControl_RevNumber" at 4982,-655.67 h60
  text "TID #:" at 2248,-859 h60
  text ".TID" at 2793.5,-859 h60
  text "PLOT NAME =" at -228.5,-1064.34 h60
  text ".plot_File_Name" at 577,-1064.34 h60
  text "GENERATED    :" at 2250,-1064.34 h60
  text ".Print_Date" at 3119.5,-1064.34 h60
  text ".Print_Time" at 3848.5,-1064.34 h60
  text "TEXAS INSTRUMENTS" at 5113,-1064.34 h60
M6 Assembly Bottom:
  lines w10: -292.5,-727.33 6309.5,-727.33 ; -290.5,-930.67 6309.5,-930.67 ; 1115.5,-1140.5 1115.5,-937.67 ; 1737.5,-727.33 1737.5,-524 ; 2577.5,-727.33 2577.5,-524 ; 3844.5,-1134 3844.5,-524 ; 4733.5,-1134 6309,-1134 6309,-524 -292.5,-524 -292.5,-1134 2304.5,-1134 6309.5,-1134 6309.5,-524
  text "COMPONENTS MARKED 'DNP' SHOULD NOT BE POPULATED." at 6102,-318 h60
  text ".VariantName" at 5058,-434 h60
  text "ASSEMBLY VARIANT:" at 6097,-434 h60
  text ".VersionControl_RevNumber" at 1035.5,-656.17 h60
  text "SVN REV:" at 1541.5,-656.17 h60
  text ".PCB_Rev" at 2088,-656.17 h60
  text "REV:" at 2379.5,-656.17 h60
  text ".PRJ_Number" at 3224,-656.17 h60
  text "BOARD #:" at 3769.5,-656.17 h60
  text "PCB VIEWED FROM BOTTOM SIDE" at 6246,-656.17 h60
  text ".TID" at 3224,-859.5 h60
  text "TID #:" at 3769.5,-859.5 h60
  text "TEXAS INSTRUMENTS" at 904.5,-1064.84 h60
  text ".Print_Time" at 2169,-1064.84 h60
  text ".Print_Date" at 2898,-1064.84 h60
  text "GENERATED    :" at 3767.5,-1064.84 h60
  text ".plot_File_Name" at 5440.5,-1064.84 h60
  text "PLOT NAME =" at 6246,-1064.84 h60
M9 Title Sheet:
  drawing of 57 lines, arcs and shapes, not listed
  text "1" at 739.84,8036.5 h70
  text "2" at 3235.5,8036.5 h70
  text "3" at 5724.84,8036.5 h70
  text "4" at 8231.51,8036.5 h70
  text "5" at 10730.5,8036.5 h70
  text "6" at 13235.5,8036.5 h70
  text "A" at -416.5,6893.5 h70
  text "A" at 14383.5,6893.5 h70
  text "B" at -416.5,4513.5 h70
  text "B" at 14383.5,4513.5 h70
  text "C" at -416.5,2138.5 h70
  text "C" at 14383.5,2138.5 h70
  text "PROJECT TITLE:" at 11343.5,277.5 h45
  text ".PRJ_Title" at 11393.5,144.17 h70
  text "DESIGNED FOR:" at 11343.5,-23.5 h45
  text ".PRJ_Customer" at 11393.5,-163.5 h70
  text "D" at -416.5,-231.5 h70
  text "D" at 14383.5,-231.5 h70
  text "FILE NAME:" at 11343.5,-323.5 h45
  text ".PCB_File_Name_No_Path" at 11393.5,-443.5 h70
  text "Texas Instruments (TI) and/or its licensors do not warrant the accuracy or completeness of this specification" at 6374,-605.34 h45
  text "ENGINEER:" at 11343.5,-613.5 h45
  text "LAYOUT BY:" at 12848.5,-613.5 h45
  text "or any information contained therein. TI and/or its licensors do not warrant that this design will meet" at 6329.01,-718 h45
  text ".PRJ_Engineer" at 11393.5,-768.49 h70
  text ".PCB_Layout" at 12899,-768.49 h70
  text "the specifications, will be suitable for your application or fit for any particular purpose, or will operate in" at 6329.01,-830.67 h45
  text ".Layer_Name" at 577,-858.49 h60
  text "ALTIUM DESIGNER VERSION:" at 12848.5,-923.5 h45
  text "an implementation. TI and/or its licensors do not warrant that the design is production worthy. You should" at 6329.01,-943.33 h45
  text "completely validate and test your design implementation to confirm the system functionality for your application." at 6374,-1056 h45
  text ".print_Scale" at 11393.5,-1056.83 h70
  text ".Application_BuildNumber" at 12899,-1056.83 h70
  text "1" at 739.84,-1263.5 h70
  text "2" at 3235.5,-1263.5 h70
  text "3" at 5724.84,-1263.5 h70
  text "4" at 8231.51,-1263.5 h70
  text "5" at 10730.5,-1263.5 h70
  text "6" at 13235.5,-1263.5 h70
M10 Fab Notes:
  drawing of 189 lines, arcs and shapes, not listed
  text "DESIGN INFORMATION" at 12382.02,6356.17 h60
  text "MIN. TRACK WIDTH:" at 11737.46,6224.05 h60
  text "8" at 12833.7,6224.05 h60
  text "MIL" at 12988.46,6224.05 h60
  text "MIN. CLEARANCE:" at 11737.46,6099.92 h60
  text "0.2" at 12773.7,6099.93 h60
  text "mm" at 12988.46,6099.92 h60
  text "MIN. VIA PAD SIZE:" at 11737.46,5975.8 h60
  text "24" at 12803.71,5975.8 h60
  text "MIL" at 12988.46,5975.8 h60
  text "0.05mm (2MIL)" at 12432.46,5845.9 h60
  text "MINIMUM ANNULAR RING" at 11408.23,5837.67 h60
  text "EXTERNAL" at 13140.46,5837.67 h60
  text "PER" at 11608.23,5727.55 h60
  text "IPC-D-275 CLASS 2 LEVEL C" at 11828.23,5727.54 h60
  text "MIL, HOLES" at 13316.46,5627.07 h60
  text "+/-" at 12924,5618.48 h60
  text "+/-" at 13778,5618.48 h60
  text "REGISTRATION TOLERANCES:" at 11408.23,5617.42 h60
  text "METAL" at 12608,5617.42 h60
  text "5" at 13184.2,5617.42 h60
  text "3" at 14017.2,5617.42 h60
  text "MIL" at 14133.46,5617.42 h60
  text "HOLE SIZE TOLERANCE (UNLESS OTHERWISE SPECIFIED):" at 11408.23,5519.1 h60
  text "+/-" at 13778,5516.23 h60
  text "3" at 14017.2,5515.17 h60
  text "MIL" at 14133.46,5515.17 h60
  text "MATERIAL:" at 11333.46,5377.52 h60
  text "FR-4 High Tg" at 12319.9,5249 h60
  text "X" at 12175.46,5241.01 h60
  text "FR-408" at 11754.46,5236.49 h60
  text "OTHER" at 13242.46,5236.49 h60
  text "62 MIL (1.6mm) +/-10%" at 12074.56,5093.46 h60
  text "X" at 11954.46,5091.01 h60
  text "THICKNESS:" at 11408.23,5085.24 h60
  text "OTHER" at 13359.46,5085.24 h60
  text "TOLERANCE:" at 11408.23,4946.92 h60
  text "X" at 12256.46,4946.92 h60
  text "ANSI IPC-6012 TYPE 3 CLASS 2" at 12434.48,4946.92 h60
  text "OTHER +/-" at 12434.46,4802.73 h60
  text "BOW & TWIST:" at 11408.23,4657.54 h60
  text "X" at 12256.46,4657.54 h60
  text "ANSI IPC-6012 TYPE 3 CLASS 2" at 12434.48,4657.54 h60
  text "OTHER +/-" at 12434.46,4510.85 h60
  text "DRILLING:" at 11333.46,4380.23 h60
  text "NC_DRILL FILES" at 13094.46,4275.04 h60
  text "REFERENCE:" at 11408.23,4271.1 h60
  text "X" at 12065.46,4271.01 h60
  text "AS SHOWN" at 12243.46,4271.1 h60
  text "X" at 12966.46,4271.1 h60
  text "OTHER" at 13392.46,4128.85 h60
  text "PTH COPPER THICKNESS:" at 11407.91,4125.32 h60
  text "X" at 12547.14,4125.32 h60
  text "20-30 um" at 12675.14,4125.32 h60
  text "BOARD FINISH:" at 11333.46,3977.73 h60
  text "SILKSCREEN:" at 11488.68,3867.6 h60
  text "X" at 12446.46,3867.6 h60
  text "TOP" at 12563.46,3867.6 h60
  text "X" at 12956.46,3867.6 h60
  text "BOTTOM" at 13074.46,3867.6 h60
  text "SILKSCREEN COLOR:" at 11488.68,3712.41 h60
  text "X" at 12445.46,3712.41 h60
  text "WHITE" at 12563.46,3712.41 h60
  text "OTHER" at 13074.46,3712.41 h60
  text "X" at 12576.46,3568.96 h60
  text "GREEN" at 12694.46,3568.96 h60
  text "OTHER" at 13312.46,3568.96 h60
  text "SOLDER RESIST COLOR:" at 11488.68,3562.1 h60
  text "X" at 12576.46,3414.71 h60
  text "MATTE" at 12694.46,3414.71 h60
  text "SEMI-GLOSS" at 13312,3414.07 h60
  text "IMMERSION GOLD (ENIG)" at 12394.46,3241.94 h60
  text "ENEPIG" at 13732,3234.72 h60
  text "SURFACE FINISH:" at 11333.46,3233.72 h60
  text "X" at 12216.46,3233.72 h60
  text "IMM. TIN/SILVER OR EQUIV" at 11663,3096.4 h60
  text "OTHER" at 13094.46,3092.47 h60
  text "ARRAY/PANEL:" at 11333.46,2937.09 h60
  text "CUT AND TRIM PER M1 BOARD OUTLINE" at 12394.46,2928.87 h60
  text "N.C. ROUTE" at 12394.46,2792.9 h60
  text "X" at 13082.46,2792.9 h60
  text "V. SCORE" at 13260.46,2792.9 h60
  text "CERTIFICATION:" at 11333.46,2663.77 h60
  text "MATERIALS AND WORKMANSHIP FOR ALL PCBS" at 12058.46,2663.77 h60
  text "TO MEET OR EXCEED THE REQUIREMENTS OF:" at 12058.46,2569.71 h60
  text "X" at 11695.97,2441.08 h60
  text "ANSI IPC-A-600F CLASS ->" at 11823.96,2441.08 h60
  text "X" at 13471.97,2441.08 h60
  text "2" at 13581.96,2441.08 h60
  text "1" at 13266.96,2439.58 h60
  text "3" at 13935.96,2439.58 h60
  text "X" at 12507.97,2293.39 h60
  text "RoHS" at 12635.96,2293.39 h60
  text "OTHER" at 13280.36,2293.39 h60
  text "PER ORDER" at 13677.42,2293.39 h60
  text "ALL BOARDS MUST MEET OR EXCEED UL94-V0 REQUIREMENTS." at 11361,2139.57 h60
  text "PCB MUST BEAR THE UL94V-0 UL REGISTERED MATERIAL ID NUMBER" at 11361,2023.5 h60
  text "ADDITIONAL REQUIREMENTS:" at 11333.46,1854.08 h60
  text "MICROSECTION:" at 11408.23,1746.95 h60
  text "YES" at 12313.96,1746.95 h60
  text "REQUIRED" at 13175.46,1602.62 h60
  text "BARE BOARD ELEC. TEST:" at 11408.23,1599.76 h60
  text "NONE" at 12713.96,1599.76 h60
  text "X" at 13057.46,1599.76 h60
  text "PER ORDER" at 13767.46,1599.76 h60
  text "XX MIL VIAS REQUIRE NON-CONDUCTIVE FILL AND PLANARIZE" at 11576.38,1394.82 h59
  text "XX MIL VIAS REQUIRE CONDUCTIVE FILL AND PLANARIZE" at 11584.38,1290.84 h60
  text "OUTER XX MIL TRACES REQUIRE 50 OHM SINGLE-ENDED IMPEDANCE" at 11583.39,1127.46 h58
  text "LAYER 2 & 3 (INNER LAYERS) XX MIL WIDE, XX MIL SPACE / TRACES REQUIRE 100 OHM DIFFERENTIAL IMPEDANCE" at 11575.39,891.74 h60
  text ".Layer_Name" at 577,-858.49 h60
M11 Gerber Information:
  lines w10: -292,-930.17 6308,-930.17 ; -292,-726.83 6310,-726.83 ; -292,-523.5 -292,-1133.5 3713,-1133.5 6310,-1133.5 6310,-523.5 -291.5,-523.5 -291.5,-1133.5 1284,-1133.5 ; 2173,-1133.5 2173,-523.5 ; 3440,-726.83 3440,-523.5 ; 4280,-726.83 4280,-523.5 ; 4902,-1140 4902,-937.17
  text "ALL ARTWORK VIEWED FROM TOP SIDE" at -228.5,-655.67 h60
  text "BOARD #:" at 2248,-655.67 h60
  text ".PRJ_Number" at 2793.5,-655.67 h60
  text "REV:" at 3638,-655.67 h60
  text ".PCB_Rev" at 3929.5,-655.67 h60
  text "SVN REV:" at 4476,-655.67 h60
  text ".VersionControl_RevNumber" at 4982,-655.67 h60
  text "LAYER NAME =" at -228.5,-858.49 h60
  text "TID #:" at 2248,-859 h60
  text ".TID" at 2793.5,-859 h60
  text "PLOT NAME =" at -228.5,-1064.34 h60
  text ".plot_File_Name" at 577,-1064.34 h60
  text "GENERATED    :" at 2250,-1064.34 h60
  text ".Print_Date" at 3119.5,-1064.34 h60
  text ".Print_Time" at 3848.5,-1064.34 h60
  text "TEXAS INSTRUMENTS" at 5113,-1064.34 h60
M12 Stackup:
  drawing of 295 lines, arcs and shapes, not listed
  text "Layer" at 5365,5755 h60
  text "Name" at 5774.91,5755 h60
  text "Material" at 6704.66,5755 h60
  text "Thickness" at 7564.42,5755 h60
  text "Constant" at 8214.26,5755 h60
  text "Board Layer Stack" at 8784.12,5755 h60
  text "1" at 5365,5635 h60
  text "Top Overlay" at 5774.91,5635 h60
  text "2" at 5365,5515 h60
  text "Top Solder" at 5774.91,5515 h60
  text "Solder Resist" at 6704.66,5515 h60
  text "0.40mil" at 7564.42,5515 h60
  text "3.5" at 8214.26,5515 h60
  text "3" at 5365,5395 h60
  text "Top Layer" at 5774.91,5395 h60
  text "Copper" at 6704.66,5395 h60
  text "1.40mil" at 7564.42,5395 h60
  text "4" at 5365,5275 h60
  text "Dielectric 1" at 5774.91,5275 h60
  text "FR-4" at 6704.66,5275 h60
  text "8.00mil" at 7564.42,5275 h60
  text "4.2" at 8214.26,5275 h60
  text "5" at 5365,5155 h60
  text "Ground" at 5774.91,5155 h60
  text "Copper" at 6704.66,5155 h60
  text "1.40mil" at 7564.42,5155 h60
  text "6" at 5365,5035 h60
  text "Dielectric 2" at 5774.91,5035 h60
  text "FR-4" at 6704.66,5035 h60
  text "40.00mil" at 7564.42,5035 h60
  text "4.2" at 8214.26,5035 h60
  text "7" at 5365,4915 h60
  text "Power" at 5774.91,4915 h60
  text "Copper" at 6704.66,4915 h60
  text "1.40mil" at 7564.42,4915 h60
  text "8" at 5365,4795 h60
  text "Dielectric 3" at 5774.91,4795 h60
  text "FR-4" at 6704.66,4795 h60
  text "8.00mil" at 7564.42,4795 h60
  text "4.2" at 8214.26,4795 h60
  text "9" at 5365,4675 h60
  text "Bottom Layer" at 5774.91,4675 h60
  text "Copper" at 6704.66,4675 h60
  text "1.40mil" at 7564.42,4675 h60
  text "10" at 5365,4555 h60
  text "Bottom Solder" at 5774.91,4555 h60
  text "Solder Resist" at 6704.66,4555 h60
  text "0.40mil" at 7564.42,4555 h60
  text "3.5" at 8214.26,4555 h60
  text "11" at 5365,4435 h60
  text "Bottom Overlay" at 5774.91,4435 h60
  text ".Layer_Name" at 577,-858.49 h60
M13 Component Bodies Top:
  text ".Layer_Name" at 577,-858.49 h60
M14 Component Bodies Bottom:
  text ".Layer_Name" at 577,-858.49 h60
M15 Courtyards Top:
  text ".Layer_Name" at 577,-858.49 h60
M16 Courtyards Bottom:
  text ".Layer_Name" at 577,-858.49 h60
Drill Drawing:
  circle w10: c5363.72,3507.55 r16.58
  circle w10: c5363.72,3507.55 r27.63
  circle w10: c5363.72,3383.23 r27.63
  lines w10: 5336.09,3010.27 5363.72,2982.64 5391.34,3010.27 5363.72,3037.9 5336.09,3010.27 ; 5336.09,3120.78 5349.9,3120.78 5349.9,3106.96 5377.53,3106.96 5377.53,3120.78 5391.34,3120.78 5391.34,3148.4 5377.53,3148.4 5377.53,3162.22 5349.9,3162.22 5349.9,3148.4 5336.09,3148.4 5336.09,3120.78 ; 5336.09,3231.28 5391.34,3231.28 5391.34,3286.54 5336.09,3286.54 5336.09,3231.28 ; 5336.09,3604.24 5336.09,3618.06 5349.9,3631.87 5336.09,3645.68 5336.09,3659.5 5349.9,3659.5 5363.72,3645.68 5377.53,3659.5 5391.34,3659.5 5391.34,3645.68 5377.53,3631.87 5391.34,3618.06 5391.34,3604.24 5377.53,3604.24 5363.72,3618.06 5349.9,3604.24 5336.09,3604.24 ; 5336.09,3742.38 5349.9,3742.38 5363.72,3728.56 5377.53,3742.38 5391.34,3742.38 5377.53,3756.19 5391.34,3770 5377.53,3770 5363.72,3783.82 5349.9,3770 5336.09,3770 5349.9,3756.19 5336.09,3742.38 ; 5336.09,3908.14 5391.34,3908.14 5363.72,3852.88 5336.09,3908.14 ; 5336.09,3977.2 5363.72,3991.02 5391.34,3977.2 5377.53,4004.83 5391.34,4032.46 5363.72,4018.64 5336.09,4032.46 5349.9,4004.83 5336.09,3977.2 ; 5336.09,4101.52 5391.34,4101.52 5391.34,4156.78 5336.09,4156.78 5336.09,4101.52 ; 5347.14,4112.57 5380.29,4112.57 5380.29,4145.73 5347.14,4145.73 5347.14,4112.57
  lines w12: 5286,2945.35 8517.49,2945.35 ; 5286,4188.55 8517.49,4188.55 ; 5623.86,2821.03 5623.86,4312.87 ; 5955.86,2821.03 5955.86,4312.87 ; 6592.43,2821.03 6592.43,4312.87 ; 6851.57,2821.03 6851.57,4312.87 ; 7226.72,2821.03 7226.72,4312.87 ; 7951.05,2821.03 7951.05,4312.87 ; 5286,2821.03 8517.49,2821.03 8517.49,4312.87 5286,4312.87 5286,2821.03
  text "Symbol" at 5360.59,4225.84 h72
  text "Quantity" at 5661.16,4225.84 h72
  text "Finished Hole Size" at 5993.16,4225.84 h72
  text "Plated" at 6629.72,4225.84 h72
  text "Hole Type" at 6888.86,4225.84 h72
  text "Drill Layer Pair" at 7264.02,4225.84 h72
  text "Hole Tolerance" at 7988.35,4225.84 h72
  text "8" at 5661.16,4101.52 h60
  text "7.87mil (0.200mm)" at 5993.16,4101.52 h60
  text "PTH" at 6629.72,4101.52 h60
  text "Round" at 6888.86,4101.52 h60
  text "Top Layer - Bottom Layer" at 7264.02,4101.52 h60
  text "631" at 5661.16,3977.2 h60
  text "10.00mil (0.254mm)" at 5993.16,3977.2 h60
  text "PTH" at 6629.72,3977.2 h60
  text "Round" at 6888.86,3977.2 h60
  text "Top Layer - Bottom Layer" at 7264.02,3977.2 h60
  text "11" at 5661.16,3852.88 h60
  text "33.47mil (0.850mm)" at 5993.16,3852.88 h60
  text "PTH" at 6629.72,3852.88 h60
  text "Round" at 6888.86,3852.88 h60
  text "Top Layer - Bottom Layer" at 7264.02,3852.88 h60
  text "75" at 5661.16,3728.56 h60
  text "40.00mil (1.016mm)" at 5993.16,3728.56 h60
  text "PTH" at 6629.72,3728.56 h60
  text "Round" at 6888.86,3728.56 h60
  text "Top Layer - Bottom Layer" at 7264.02,3728.56 h60
  text "2" at 5661.16,3604.24 h60
  text "40.16mil (1.020mm)" at 5993.16,3604.24 h60
  text "PTH" at 6629.72,3604.24 h60
  text "Round" at 6888.86,3604.24 h60
  text "Top Layer - Bottom Layer" at 7264.02,3604.24 h60
  text "6" at 5661.16,3479.92 h60
  text "49.21mil (1.250mm)" at 5993.16,3479.92 h60
  text "PTH" at 6629.72,3479.92 h60
  text "Round" at 6888.86,3479.92 h60
  text "Top Layer - Bottom Layer" at 7264.02,3479.92 h60
  text "8" at 5661.16,3355.6 h60
  text "51.18mil (1.300mm)" at 5993.16,3355.6 h60
  text "PTH" at 6629.72,3355.6 h60
  text "Round" at 6888.86,3355.6 h60
  text "Top Layer - Bottom Layer" at 7264.02,3355.6 h60
  text "3" at 5661.16,3231.28 h60
  text "63.00mil (1.600mm)" at 5993.16,3231.28 h60
  text "PTH" at 6629.72,3231.28 h60
  text "Round" at 6888.86,3231.28 h60
  text "Top Layer - Bottom Layer" at 7264.02,3231.28 h60
  text "4" at 5661.16,3106.96 h60
  text "125.98mil (3.200mm)" at 5993.16,3106.96 h60
  text "PTH" at 6629.72,3106.96 h60
  text "Round" at 6888.86,3106.96 h60
  text "Top Layer - Bottom Layer" at 7264.02,3106.96 h60
  text "2" at 5661.16,2982.64 h60
  text "23.62mil (0.600mm)" at 5993.16,2982.64 h60
  text "PTH" at 6629.72,2982.64 h60
  text "Slot" at 6888.86,2982.64 h60
  text "Top Layer - Bottom Layer" at 7264.02,2982.64 h60
  text "750 Total" at 5661.16,2858.32 h60
  text "Slot definitions :" at 5360.59,2771.3 h60
  text "Routed Path Length" at 5811.31,2771.3 h60
  text "= Calculated from tool start centre position to tool end centre position." at 6351.05,2771.3 h60
  text "Hole Length" at 5811.31,2721.57 h60
  text "= Routed Path Length + Tool Size = Slot length as defined in the PCB layout" at 6151.24,2721.57 h60
  text ".Layer_Name" at 577,-858.49 h60
Mechanical 17:
  text ".Layer_Name" at 577,-858.49 h60
Mechanical 18:
  text ".Layer_Name" at 577,-858.49 h60
Mechanical 19:
  text ".Layer_Name" at 577,-858.49 h60

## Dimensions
0,2850 to 4255,0 on M2 Board Dimensions
4255,0 to 0,2850 on M2 Board Dimensions
0,-400 to 1000,-400 on M2 Board Dimensions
